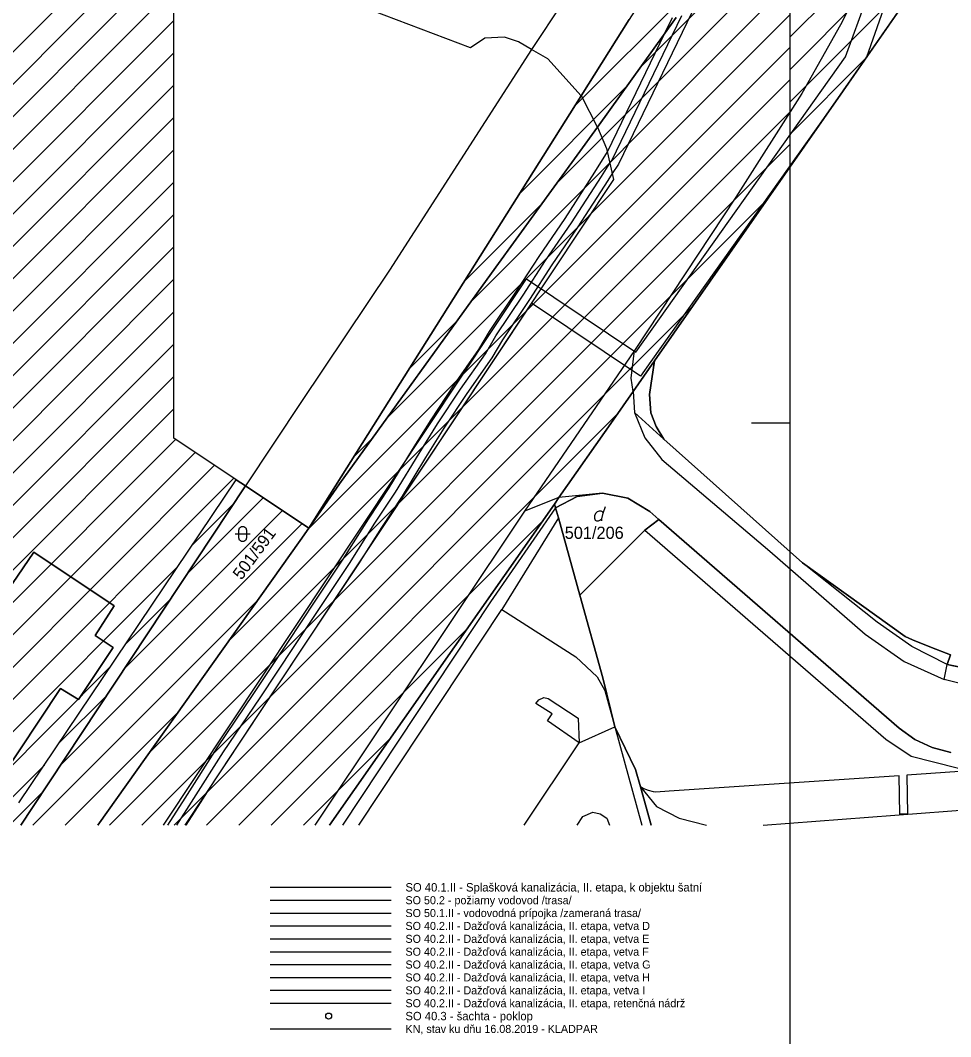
# Model space of a CAD drawing. Extents: x -264309 to -263505, y -1242443 to -1241763.
# Drawn here: x -263786.7 to -263664.7, y -1242279.4 to -1242146.2 of the extents above; entities that cross this region are included whole.
import ezdxf

# ---------------------------------------------------------------- set-up
doc = ezdxf.new("R2010")
doc.units = 0
for name, color, linetype in [('KN_2019_08_16', 7, 'Continuous'), ('KN_2019_08_16_KLADPAR', 7, 'Continuous'), ('KN_2019_08_16_ZAPPAR', 7, 'Continuous'), ('LEGENDA', 7, 'Continuous'), ('RAM_NA_TLAC_10xA4_1-500', 7, 'Continuous'), ('SRAFY_PARCELY', 7, 'Continuous')]:
    doc.layers.add(name, color=color, linetype=linetype)

msp = doc.modelspace()

# ---------------------------------------------------------------- linework, layer by layer
at = {"layer": 'KN_2019_08_16'}
for p, q in [((-263678.53, -1242150.99), (-263670.89, -1242130.32)), ((-263668.72, -1242131.08), (-263675.77, -1242151.07)), ((-263705.99, -1242189.73), (-263678.53, -1242150.99)), ((-263675.77, -1242151.07), (-263678.83, -1242155.48)), ((-263678.83, -1242155.48), (-263704.05, -1242190.96)), ((-263767.93, -1242251.71), (-263720.34, -1242180.11)), ((-263720.34, -1242180.11), (-263705.99, -1242189.73)), ((-263719.7, -1242183.29), (-263749.84, -1242228.66)), ((-263705.39, -1242192.88), (-263719.7, -1242183.29)), ((-263704.05, -1242190.96), (-263705.39, -1242192.88)), ((-263749.84, -1242228.66), (-263765.16, -1242251.71)), ((-263713.45, -1242240.91), (-263708.75, -1242238.83)), ((-263708.75, -1242238.83), (-263706.04, -1242244.41)), ((-263720.63, -1242251.71), (-263713.45, -1242240.91)), ((-263706.04, -1242244.41), (-263705.4, -1242246.7)), ((-263689.32, -1242251.71), (-263607.55, -1242245.57)), ((-263705.4, -1242246.7), (-263704, -1242251.71)), ((-263704, -1242251.71), (-263705.4, -1242246.7)), ((-263705.4, -1242246.7), (-263703.29, -1242249.25)), ((-263703.29, -1242249.25), (-263700.34, -1242250.78)), ((-263700.34, -1242250.78), (-263696.72, -1242251.71))]:
    msp.add_line(p, q, dxfattribs=at)
for points in [[(-263767.38, -1242251.71), (-263765.12, -1242248.17), (-263760.91, -1242241.56), (-263756.12, -1242234.47), (-263751.66, -1242227.76), (-263748.04, -1242222.35), (-263744.39, -1242216.87), (-263741.06, -1242211.61), (-263738.35, -1242207.51), (-263735.29, -1242202.48), (-263732.86, -1242198.59), (-263729.81, -1242194), (-263726.58, -1242189.38), (-263725.2, -1242187.03), (-263721.64, -1242181.7), (-263718.7, -1242177.17), (-263715.29, -1242172.21), (-263711.37, -1242166.13), (-263709.74, -1242163.47), (-263702.21, -1242147.92), (-263701.21, -1242145.86)], [(-263766.2, -1242251.71), (-263764.28, -1242248.71), (-263760.07, -1242242.11), (-263755.29, -1242235.03), (-263750.83, -1242228.31), (-263747.21, -1242222.91), (-263743.55, -1242217.41), (-263740.22, -1242212.15), (-263737.51, -1242208.05), (-263734.44, -1242203), (-263732.02, -1242199.13), (-263728.98, -1242194.56), (-263725.74, -1242189.92), (-263724.35, -1242187.56), (-263720.8, -1242182.25), (-263717.87, -1242177.72), (-263714.46, -1242172.76), (-263710.53, -1242166.68), (-263709.4, -1242164.95), (-263709.17, -1242164.6), (-263699.96, -1242145.6)], [(-263698.67, -1242145.2), (-263708.3, -1242165.09), (-263709.09, -1242166.31), (-263709.69, -1242167.23), (-263713.63, -1242173.31), (-263717.04, -1242178.27), (-263719.96, -1242182.8), (-263723.5, -1242188.09), (-263724.9, -1242190.46), (-263728.15, -1242195.12), (-263731.18, -1242199.67), (-263733.59, -1242203.52), (-263736.67, -1242208.59), (-263739.38, -1242212.69), (-263742.38, -1242217.44), (-263749.84, -1242228.66), (-263761.3, -1242245.9)], [(-263761.3, -1242245.9), (-263763.44, -1242249.25), (-263765.02, -1242251.71)]]:
    msp.add_lwpolyline(points, dxfattribs=at)
at = {"layer": 'KN_2019_08_16_KLADPAR'}
for p, q in [((-263678.83, -1242155.48), (-263666.12, -1242137.18)), ((-263703.55, -1242190.87), (-263678.83, -1242155.48)), ((-263704.21, -1242195.25), (-263703.55, -1242190.87)), ((-263704.05, -1242197.65), (-263704.21, -1242195.25)), ((-263703.33, -1242199.46), (-263704.05, -1242197.65)), ((-263702.35, -1242201.12), (-263703.33, -1242199.46)), ((-263684.17, -1242217.32), (-263702.35, -1242201.12)), ((-263786.91, -1242248.79), (-263758.42, -1242206.43)), ((-263758.42, -1242206.43), (-263757.19, -1242207.25)), ((-263757.19, -1242207.25), (-263785.11, -1242249.39)), ((-263746.16, -1242251.71), (-263716.69, -1242209.63)), ((-263716.69, -1242209.63), (-263716.55, -1242210.1)), ((-263716.55, -1242210.1), (-263716.15, -1242211.42)), ((-263710.27, -1242210.84), (-263710, -1242209.94)), ((-263716.15, -1242211.42), (-263713.34, -1242221.57)), ((-263704.81, -1242213.03), (-263702.99, -1242211.63)), ((-263702.99, -1242211.63), (-263671.48, -1242238.99)), ((-263713.34, -1242221.57), (-263704.81, -1242213.03)), ((-263670.67, -1242226.98), (-263684.17, -1242217.32)), ((-263713.34, -1242221.57), (-263710.35, -1242232.41)), ((-263710.35, -1242232.41), (-263713.34, -1242221.57)), ((-263669.74, -1242227.41), (-263670.67, -1242226.98)), ((-263667.25, -1242228.44), (-263669.74, -1242227.41)), ((-263664.73, -1242229.38), (-263667.25, -1242228.44)), ((-263665.17, -1242230.64), (-263664.73, -1242229.38)), ((-263655.72, -1242232.61), (-263665.17, -1242230.64)), ((-263710.35, -1242232.41), (-263708.75, -1242238.83)), ((-263708.75, -1242238.83), (-263710.35, -1242232.41)), ((-263708.75, -1242238.83), (-263706.04, -1242244.41)), ((-263706.04, -1242244.41), (-263708.75, -1242238.83)), ((-263671.48, -1242238.99), (-263669.43, -1242240.47)), ((-263669.43, -1242240.47), (-263667.15, -1242241.55)), ((-263667.15, -1242241.55), (-263664.7, -1242242.17)), ((-263706.04, -1242244.41), (-263705.4, -1242246.7)), ((-263705.4, -1242246.7), (-263706.04, -1242244.41)), ((-263705.4, -1242246.7), (-263704, -1242251.71)), ((-263704, -1242251.71), (-263705.4, -1242246.7)), ((-263785.11, -1242249.39), (-263786.65, -1242251.71))]:
    msp.add_line(p, q, dxfattribs=at)
for points in [[(-263766.58, -1242082.89), (-263701.19, -1242089.29), (-263698.34, -1242093.87), (-263688.51, -1242109.63), (-263692.31, -1242120.01), (-263699.84, -1242134.09), (-263703.22, -1242140.34), (-263706.87, -1242146.12), (-263713.18, -1242156.13), (-263748.89, -1242212.77), (-263757.19, -1242207.25), (-263758.42, -1242206.43), (-263766.58, -1242201.01), (-263766.58, -1242144.85), (-263766.58, -1242122.39), (-263766.58, -1242113.95), (-263766.58, -1242093.5)], [(-263713.34, -1242221.57), (-263716.15, -1242211.42), (-263716.55, -1242210.1), (-263713.71, -1242208.64), (-263710.36, -1242208.18), (-263707.05, -1242208.87), (-263704.18, -1242210.6), (-263702.99, -1242211.63), (-263704.81, -1242213.03)], [(-263758.07, -1242213.05), (-263757.97, -1242212.76), (-263757.72, -1242212.58), (-263757.41, -1242212.58), (-263757.16, -1242212.76), (-263757.06, -1242213.05), (-263757.06, -1242214.05), (-263757.16, -1242214.34), (-263757.41, -1242214.52), (-263757.72, -1242214.52), (-263757.97, -1242214.34), (-263758.07, -1242214.05)], [(-263784.95, -1242215.92), (-263774.44, -1242222.95), (-263776.9, -1242226.85), (-263774.55, -1242228.43), (-263779.09, -1242235.23), (-263781.45, -1242233.8), (-263789.58, -1242245.99), (-263800.48, -1242238.67)], [(-263774.44, -1242222.95), (-263784.95, -1242215.92), (-263800.48, -1242238.67), (-263789.58, -1242245.99), (-263781.45, -1242233.8), (-263779.09, -1242235.23), (-263774.55, -1242228.43), (-263776.9, -1242226.85)]]:
    msp.add_lwpolyline(points, close=True, dxfattribs=at)
for points in [[(-263666.12, -1242137.18), (-263678.83, -1242155.48), (-263703.55, -1242190.87), (-263706.35, -1242194.87), (-263708.98, -1242198.62), (-263716.1, -1242208.78), (-263716.69, -1242209.63), (-263746.16, -1242251.71)], [(-263776.55, -1242251.71), (-263750.03, -1242214.41), (-263748.89, -1242212.77), (-263744.87, -1242206.99), (-263724.36, -1242178.58), (-263711.04, -1242160.22), (-263700.71, -1242145.84)], [(-263700.71, -1242145.84), (-263711.04, -1242160.22), (-263724.36, -1242178.58), (-263744.87, -1242206.99), (-263748.89, -1242212.77), (-263713.18, -1242156.13), (-263706.87, -1242146.12)], [(-263664.7, -1242242.17), (-263667.15, -1242241.55), (-263669.43, -1242240.47), (-263671.48, -1242238.99), (-263702.99, -1242211.63), (-263704.18, -1242210.6), (-263707.05, -1242208.87), (-263710.36, -1242208.18), (-263713.71, -1242208.64), (-263716.55, -1242210.1), (-263716.69, -1242209.63), (-263716.1, -1242208.78), (-263708.98, -1242198.62), (-263706.35, -1242194.87), (-263703.55, -1242190.87), (-263704.21, -1242195.25), (-263704.05, -1242197.65), (-263703.33, -1242199.46), (-263702.35, -1242201.12), (-263684.17, -1242217.32), (-263670.67, -1242226.98), (-263669.74, -1242227.41), (-263667.25, -1242228.44), (-263664.73, -1242229.38), (-263665.17, -1242230.64), (-263655.72, -1242232.61)], [(-263786.65, -1242251.71), (-263785.11, -1242249.39), (-263757.19, -1242207.25), (-263748.89, -1242212.77)], [(-263710.45, -1242211.83), (-263710.45, -1242211.56), (-263710.27, -1242210.84), (-263710.36, -1242210.66), (-263710.54, -1242210.57), (-263710.81, -1242210.57), (-263711.08, -1242210.66), (-263711.26, -1242210.84), (-263711.44, -1242211.11), (-263711.44, -1242211.47), (-263711.35, -1242211.74), (-263711.17, -1242211.83), (-263710.9, -1242211.83), (-263710.72, -1242211.74), (-263710.45, -1242211.56)], [(-263748.89, -1242212.77), (-263750.03, -1242214.41), (-263776.55, -1242251.71)], [(-263758.57, -1242213.55), (-263757.3, -1242213.55), (-263756.57, -1242213.55)]]:
    msp.add_lwpolyline(points, dxfattribs=at)
at = {"layer": 'KN_2019_08_16_ZAPPAR'}
for p, q in [((-263670.89, -1242130.32), (-263679.16, -1242146.82)), ((-263713.1, -1242156.22), (-263713.18, -1242156.13)), ((-263711.04, -1242160.22), (-263713.1, -1242156.22)), ((-263708.92, -1242167.07), (-263749.84, -1242228.66)), ((-263706.17, -1242189.5), (-263720.6, -1242210.57)), ((-263702.35, -1242201.12), (-263706.2, -1242197.63)), ((-263710.36, -1242208.18), (-263716.1, -1242208.78)), ((-263716.1, -1242208.78), (-263720.6, -1242210.57)), ((-263720.6, -1242210.57), (-263748.12, -1242251.71)), ((-263716.55, -1242210.1), (-263725.05, -1242222.45)), ((-263716.15, -1242211.42), (-263723.59, -1242223.45)), ((-263704.81, -1242213.03), (-263673.22, -1242240.46)), ((-263688.45, -1242215.81), (-263675.94, -1242226.69)), ((-263725.05, -1242222.45), (-263744.49, -1242251.71)), ((-263665.17, -1242230.64), (-263669.83, -1242228.28)), ((-263713.45, -1242240.91), (-263717.6, -1242238.06)), ((-263708.75, -1242238.83), (-263705.21, -1242251.71)), ((-263671.47, -1242245.27), (-263701.64, -1242247.27))]:
    msp.add_line(p, q, dxfattribs=at)
for points in [[(-263698.34, -1242093.87), (-263715.64, -1242143.92), (-263719.68, -1242150.03), (-263738.33, -1242178.96)], [(-263713.18, -1242156.13), (-263717.55, -1242151.26), (-263719.68, -1242150.03), (-263721.39, -1242149.06), (-263723.21, -1242148.44), (-263725.82, -1242148.54), (-263727.71, -1242149.84), (-263740.62, -1242144.92), (-263741.22, -1242144.43), (-263743.99, -1242142.15), (-263745.98, -1242139.12), (-263746.48, -1242137.32), (-263747.89, -1242134.32), (-263749.97, -1242132.12)], [(-263679.16, -1242146.82), (-263684.22, -1242155.81), (-263692.89, -1242169.42), (-263706.17, -1242189.5)], [(-263711.04, -1242160.22), (-263709.84, -1242163.01), (-263708.92, -1242167.07)], [(-263738.33, -1242178.96), (-263749.86, -1242196.2), (-263757.19, -1242207.25)], [(-263706.35, -1242194.87), (-263706.6, -1242193.14), (-263706.17, -1242189.5)], [(-263706.35, -1242194.87), (-263706.2, -1242197.63), (-263704.82, -1242200.94), (-263702.61, -1242203.77), (-263688.45, -1242215.81)], [(-263669.83, -1242228.28), (-263674.34, -1242225.09), (-263684.17, -1242217.32)], [(-263742.34, -1242251.71), (-263723.59, -1242223.45), (-263713.89, -1242229.64)], [(-263675.94, -1242226.69), (-263670.83, -1242230.27), (-263665.58, -1242232.61)], [(-263749.84, -1242228.66), (-263765.16, -1242251.71)], [(-263713.89, -1242229.64), (-263711.09, -1242232.27), (-263710.05, -1242234.08), (-263708.75, -1242238.83)], [(-263660.13, -1242233.99), (-263665.58, -1242232.61), (-263665.17, -1242230.64)], [(-263719.1, -1242235.78), (-263718.74, -1242235.28), (-263718.06, -1242234.97), (-263717.49, -1242235.11), (-263713.59, -1242237.69), (-263713.45, -1242240.91)], [(-263717.6, -1242238.06), (-263716.96, -1242237.12), (-263719.1, -1242235.78)], [(-263673.22, -1242240.46), (-263669.9, -1242242.67), (-263663.88, -1242244.2), (-263662.27, -1242244.61), (-263670.46, -1242245.18), (-263670.39, -1242250.29), (-263671.38, -1242250.29), (-263671.47, -1242245.27)], [(-263701.64, -1242247.27), (-263703.37, -1242247.39), (-263703.71, -1242247.33), (-263704.36, -1242247.17), (-263705.05, -1242246.89), (-263705.4, -1242246.7)], [(-263713.71, -1242251.71), (-263712.95, -1242250.56), (-263711.63, -1242249.99)], [(-263711.63, -1242249.99), (-263710.7, -1242250.21), (-263709.81, -1242250.79), (-263709.48, -1242251.71)]]:
    msp.add_lwpolyline(points, dxfattribs=at)
at = {"layer": 'LEGENDA'}
for p, q in [((-263753.96, -1242259.86), (-263738.1, -1242259.86)), ((-263753.96, -1242261.55), (-263738.1, -1242261.55)), ((-263753.96, -1242263.24), (-263738.1, -1242263.24)), ((-263753.96, -1242264.92), (-263738.1, -1242264.92)), ((-263753.96, -1242266.61), (-263738.1, -1242266.61)), ((-263753.96, -1242268.3), (-263738.1, -1242268.3)), ((-263753.96, -1242269.99), (-263738.1, -1242269.99)), ((-263753.96, -1242271.67), (-263738.1, -1242271.67)), ((-263753.96, -1242273.36), (-263738.1, -1242273.36)), ((-263753.96, -1242275.05), (-263738.1, -1242275.05)), ((-263753.96, -1242278.42), (-263738.1, -1242278.42))]:
    msp.add_line(p, q, dxfattribs=at)
msp.add_circle((-263746.29, -1242276.74), 0.392, dxfattribs=at)
at = {"layer": 'RAM_NA_TLAC_10xA4_1-500'}
msp.add_line((-263685.83, -1242199.04), (-263690.83, -1242199.04), dxfattribs=at)
msp.add_lwpolyline([(-264210.83, -1242050.54), (-264105.83, -1242050.54), (-264000.83, -1242050.54), (-263895.83, -1242050.54), (-263790.83, -1242050.54), (-263685.83, -1242050.54), (-263685.83, -1242199.04), (-263685.83, -1242347.54), (-263790.83, -1242347.54), (-263895.83, -1242347.54), (-264000.83, -1242347.54), (-264105.83, -1242347.54), (-264210.83, -1242347.54), (-264210.83, -1242199.04)], close=True, dxfattribs=at)
at = {"layer": 'SRAFY_PARCELY'}
for p, q in [((-263685.83, -1242148.45), (-263646.94, -1242109.57)), ((-263685.83, -1242152.69), (-263656.59, -1242123.45)), ((-263705.41, -1242152.38), (-263685.83, -1242132.8)), ((-263716.41, -1242167.63), (-263685.83, -1242137.04)), ((-263685.83, -1242156.93), (-263666.23, -1242137.34)), ((-263714.04, -1242157.49), (-263696.41, -1242139.87)), ((-263727.57, -1242183.03), (-263685.83, -1242141.28)), ((-263854.35, -1242217.02), (-263782.48, -1242145.16)), ((-263854.26, -1242221.18), (-263778.16, -1242145.07)), ((-263854.17, -1242225.33), (-263773.83, -1242144.99)), ((-263854.09, -1242229.49), (-263769.5, -1242144.91)), ((-263766.58, -1242201.01), (-263766.58, -1242144.85)), ((-263738.58, -1242198.28), (-263685.83, -1242145.52)), ((-263854, -1242233.64), (-263766.58, -1242146.23)), ((-263749.03, -1242212.97), (-263685.83, -1242149.77)), ((-263853.91, -1242237.8), (-263766.58, -1242150.47)), ((-263685.83, -1242161.18), (-263675.88, -1242151.23)), ((-263853.83, -1242241.96), (-263766.58, -1242154.71)), ((-263759.39, -1242227.57), (-263685.83, -1242154.01)), ((-263721.28, -1242168.97), (-263707.26, -1242154.95)), ((-263853.74, -1242246.11), (-263766.58, -1242158.95)), ((-263769.82, -1242242.25), (-263685.83, -1242158.25)), ((-263775.04, -1242251.71), (-263685.83, -1242162.49)), ((-263853.65, -1242250.27), (-263766.58, -1242163.2)), ((-263685.83, -1242165.42), (-263685.65, -1242165.25)), ((-263853.56, -1242254.42), (-263766.58, -1242167.44)), ((-263770.8, -1242251.71), (-263688.7, -1242169.62)), ((-263728.52, -1242180.46), (-263718.33, -1242170.27)), ((-263853.48, -1242258.58), (-263766.58, -1242171.68)), ((-263853.39, -1242262.73), (-263766.58, -1242175.92)), ((-263853.3, -1242266.89), (-263766.58, -1242180.17)), ((-263853.21, -1242271.04), (-263766.58, -1242184.41)), ((-263766.56, -1242251.71), (-263698.53, -1242183.69)), ((-263735.76, -1242191.94), (-263729.45, -1242185.63)), ((-263853.13, -1242275.2), (-263766.58, -1242188.65)), ((-263853.04, -1242279.35), (-263766.58, -1242192.89)), ((-263852.95, -1242283.51), (-263766.58, -1242197.14)), ((-263762.31, -1242251.71), (-263708.41, -1242197.81)), ((-263838.81, -1242273.61), (-263766.36, -1242201.16)), ((-263758.42, -1242206.43), (-263766.58, -1242201.01)), ((-263742.99, -1242203.42), (-263740.47, -1242200.89)), ((-263834.75, -1242273.79), (-263763.81, -1242202.85)), ((-263830.56, -1242273.85), (-263761.26, -1242204.54)), ((-263826, -1242273.53), (-263758.71, -1242206.24)), ((-263786.91, -1242248.79), (-263758.42, -1242206.43)), ((-263764.76, -1242218.67), (-263754.88, -1242208.79)), ((-263764.2, -1242215.03), (-263758.69, -1242209.52)), ((-263773.09, -1242231.24), (-263752.33, -1242210.48)), ((-263781.42, -1242243.82), (-263749.78, -1242212.18)), ((-263758.07, -1242251.71), (-263718.33, -1242211.97)), ((-263820.81, -1242272.58), (-263766.14, -1242217.91)), ((-263785.07, -1242251.71), (-263755.59, -1242222.23)), ((-263772.92, -1242227.99), (-263767.02, -1242222.09)), ((-263753.83, -1242251.71), (-263728.24, -1242226.12)), ((-263810.88, -1242266.89), (-263774.86, -1242230.87)), ((-263781.63, -1242240.94), (-263775.35, -1242234.66)), ((-263780.83, -1242251.71), (-263766.03, -1242236.91)), ((-263749.58, -1242251.71), (-263738.15, -1242240.28)), ((-263807.48, -1242267.73), (-263783.57, -1242243.83)), ((-263788.16, -1242251.71), (-263783.68, -1242247.24)), ((-263776.58, -1242251.71), (-263776.46, -1242251.59))]:
    msp.add_line(p, q, dxfattribs=at)

# ---------------------------------------------------------------- texts
at = {"layer": 'KN_2019_08_16_KLADPAR'}
msp.add_text('501/591', height=1.6, rotation=53.3997, dxfattribs=at).set_placement((-263757.72, -1242219.67))
msp.add_text('501/206', height=1.6, dxfattribs=at).set_placement((-263715.33, -1242214.19))
at = {"layer": 'LEGENDA'}
for s, height, p in [('SO 40.1.II - Splašková kanalizácia, II. etapa, k objektu šatní', 1.1021, (-263736.22, -1242260.41)), ('SO 50.2 - požiarny vodovod /trasa/', 1.0547, (-263736.22, -1242262.08)), ('SO 50.1.II - vodovodná prípojka /zameraná trasa/', 1.0547, (-263736.22, -1242263.76)), ('SO 40.2.II - Dažďová kanalizácia, II. etapa, vetva D', 1.0547, (-263736.22, -1242265.45)), ('SO 40.2.II - Dažďová kanalizácia, II. etapa, vetva E', 1.0547, (-263736.22, -1242267.14)), ('SO 40.2.II - Dažďová kanalizácia, II. etapa, vetva F', 1.0547, (-263736.22, -1242268.83)), ('SO 40.2.II - Dažďová kanalizácia, II. etapa, vetva G', 1.0547, (-263736.22, -1242270.51)), ('SO 40.2.II - Dažďová kanalizácia, II. etapa, vetva H', 1.0547, (-263736.22, -1242272.2)), ('SO 40.2.II - Dažďová kanalizácia, II. etapa, vetva I', 1.0547, (-263736.22, -1242273.89)), ('SO 40.2.II - Dažďová kanalizácia, II. etapa, retenčná nádrž', 1.0547, (-263736.22, -1242275.58)), ('SO 40.3 - šachta - poklop', 1.1021, (-263736.22, -1242277.29)), ('KN, stav ku dňu 16.08.2019 - KLADPAR', 1.0547, (-263736.22, -1242278.95))]:
    msp.add_text(s, height=height, dxfattribs=at).set_placement(p)

doc.saveas('drawing.dxf')
